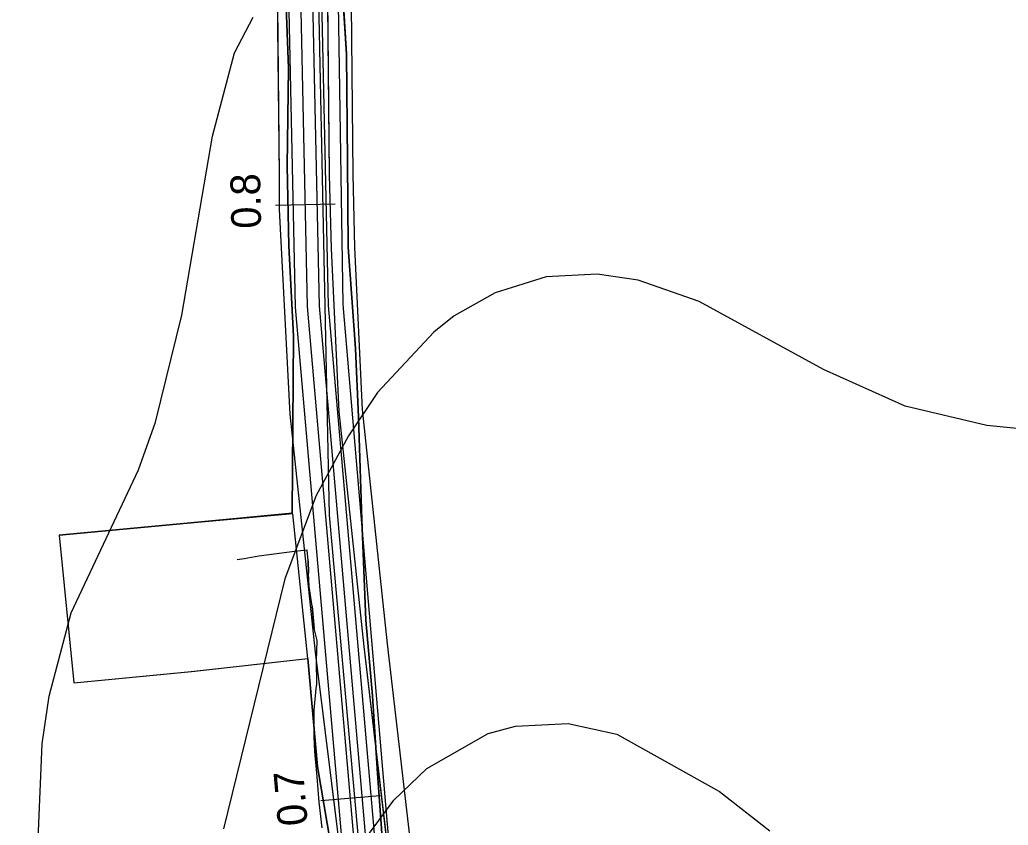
# Model space of a CAD drawing. Extents: x -662620 to -656370, y -1067090 to -1062990.
# Drawn here: x -660531.2 to -660365.2, y -1064371.3 to -1064236 of the extents above; entities that cross this region are included whole.
import ezdxf

# ---------------------------------------------------------------- set-up
doc = ezdxf.new("R2010")
doc.units = 0
for name, color, linetype in [('CESTA_ZABOR', 7, 'Continuous'), ('Default', 7, 'Continuous'), ('Krajinná_zeleň_-_liniová_-_návrh', 7, 'Continuous'), ('OBVOD_PÚ', 7, 'Continuous'), ('Ochr__pás__vod__zdroje_II__stupně', 7, 'Continuous'), ('Odvodnení_cesty_príkopem_-_navržené', 7, 'Continuous'), ('ORNÁ_PŮDA_-_STÁVAJÍCÍ', 7, 'Continuous'), ('OSTATNÍ_PLOCHA_-_NAVRŽENÁ', 7, 'Continuous'), ('OSTATNÍ_PLOCHA_-_STÁVAJÍCÍ', 7, 'Continuous'), ('POLNÍ_CESTA_NAVRŽENÁ_-_OSA', 7, 'Continuous'), ('POLNÍ_CESTA_STÁVAJÍCÍ_-_KRAJ', 7, 'Continuous'), ('SDELOVACÍ_VEDENÍ_-_PODZEMNÍ', 7, 'Continuous'), ('Trvalý_trávní_porost_-_stávající', 7, 'Continuous'), ('VRSTEVNICE_ZÁKLADNÍ', 7, 'Continuous')]:
    doc.layers.add(name, color=color, linetype=linetype)

msp = doc.modelspace()

# ---------------------------------------------------------------- linework, layer by layer
at = {"layer": 'CESTA_ZABOR'}
for p, q in [((-660487.56, -1064262.16), (-660487.99, -1064222.18)), ((-660479.6, -1064222.07), (-660479.22, -1064262.06)), ((-660487.55, -1064267.89), (-660487.56, -1064262.16)), ((-660479.22, -1064262.06), (-660478.9, -1064274.43)), ((-660485.81, -1064302.25), (-660487.55, -1064267.89)), ((-660478.9, -1064274.43), (-660477.62, -1064301.81)), ((-660481.51, -1064342.23), (-660485.81, -1064302.25)), ((-660477.62, -1064301.81), (-660473.42, -1064341.28)), ((-660476.62, -1064381.82), (-660481.51, -1064342.23)), ((-660473.42, -1064341.28), (-660468.75, -1064381.18))]:
    msp.add_line(p, q, dxfattribs=at)
for points in [[(-660476.62, -1064381.82), (-660481.51, -1064342.23), (-660485.81, -1064302.25), (-660487.55, -1064267.89), (-660487.56, -1064262.16), (-660487.99, -1064222.18), (-660488.92, -1064182.19), (-660489.62, -1064142.29), (-660490.79, -1064127.68), (-660489.61, -1064120.63), (-660489.74, -1064102.3), (-660489.62, -1064062.36), (-660491.41, -1064022.4), (-660491.82, -1063995.6), (-660491.58, -1063993.71), (-660486.92, -1063981.87), (-660480, -1063962.07), (-660476.39, -1063948.94), (-660467.64, -1063925.93), (-660459.11, -1063911.53), (-660457.57, -1063907.35), (-660441.43, -1063870.67), (-660426.53, -1063833.6), (-660410.61, -1063796.9)], [(-660402.21, -1063800.45), (-660418.38, -1063837.05), (-660433.34, -1063874.17), (-660449.71, -1063910.53), (-660464.44, -1063947.85), (-660478.91, -1063984.7), (-660482.04, -1063997.01), (-660482.49, -1064022.32), (-660480.31, -1064062.11), (-660478.98, -1064102.23), (-660479.21, -1064121.73), (-660481.5, -1064129.07), (-660481.76, -1064141.99), (-660480.35, -1064182.06), (-660479.6, -1064222.07), (-660479.22, -1064262.06), (-660478.9, -1064274.43), (-660477.62, -1064301.81), (-660473.42, -1064341.28), (-660468.75, -1064381.18)]]:
    msp.add_lwpolyline(points, dxfattribs=at)
at = {"layer": 'Krajinná_zeleň_-_liniová_-_návrh'}
msp.add_lwpolyline([(-660463.41, -1064442), (-660476.87, -1064283.86), (-660479.09, -1064143.11)], dxfattribs=at)
at = {"layer": 'OBVOD_PÚ'}
for points in [[(-660485.34, -1064319.01), (-660524.58, -1064322.57)], [(-660482.83, -1064343.31), (-660485.34, -1064319.01)], [(-660524.58, -1064322.57), (-660522.09, -1064347.37)], [(-660502.37, -1064345.51), (-660482.83, -1064343.31)], [(-660522.09, -1064347.37), (-660502.37, -1064345.51)]]:
    msp.add_lwpolyline(points, dxfattribs=at)
at = {"layer": 'Ochr__pás__vod__zdroje_II__stupně'}
msp.add_lwpolyline([(-660464.98, -1064477.66), (-660479.16, -1064319.24), (-660481.94, -1064186.81), (-660479.3, -1063994.59), (-660360.21, -1063702.35), (-660281.08, -1063700.79), (-660243.47, -1063702.35), (-660222.31, -1063711.76), (-660211.34, -1063724.29), (-660187.06, -1063774.43), (-660164.34, -1063811.26), (-660075.02, -1063846.52), (-660042.89, -1063862.97), (-660047.59, -1063878.64), (-659927.67, -1063941.34), (-659907.68, -1063958.21), (-659897.75, -1063968.57), (-659822.34, -1063992.17), (-659732.05, -1064020.39)], dxfattribs=at)
at = {"layer": 'Odvodnení_cesty_príkopem_-_navržené'}
msp.add_lwpolyline([(-660558.09, -1065055.87), (-660475.04, -1064666.65), (-660471.14, -1064652.96), (-660465.99, -1064629.97), (-660464, -1064613.86), (-660457.68, -1064584.26), (-660456.26, -1064575.18), (-660454.42, -1064557.77), (-660456.24, -1064538.9), (-660463.06, -1064471.1), (-660479.37, -1064283.99), (-660482.8, -1064124.36), (-660484.72, -1064013.14), (-660484.26, -1063999.81), (-660482.47, -1063990.24), (-660478.65, -1063978.94), (-660368.35, -1063708.74)], dxfattribs=at)
at = {"layer": 'ORNÁ_PŮDA_-_STÁVAJÍCÍ'}
for p, q in [((-660476.34, -1064241.78), (-660477.34, -1064225.29)), ((-660476.13, -1064259.82), (-660476.34, -1064241.78)), ((-660476.03, -1064274.2), (-660476.13, -1064259.82)), ((-660474.79, -1064291.24), (-660476.03, -1064274.2)), ((-660474.29, -1064302.76), (-660474.79, -1064291.24)), ((-660473.74, -1064320.03), (-660474.29, -1064302.76)), ((-660473.08, -1064336.89), (-660473.74, -1064320.03)), ((-660471.94, -1064349.57), (-660473.08, -1064336.89)), ((-660471.09, -1064362.63), (-660471.94, -1064349.57)), ((-660470.29, -1064374.22), (-660471.09, -1064362.63))]:
    msp.add_line(p, q, dxfattribs=at)
msp.add_lwpolyline([(-660470.29, -1064374.22), (-660471.09, -1064362.63), (-660471.94, -1064349.57), (-660473.08, -1064336.89), (-660473.74, -1064320.03), (-660474.29, -1064302.76), (-660474.79, -1064291.24), (-660476.03, -1064274.2), (-660476.13, -1064259.82), (-660476.34, -1064241.78), (-660477.34, -1064225.29), (-660476.74, -1064216.04), (-660477.47, -1064194.07), (-660477.33, -1064171.48), (-660477.69, -1064150.75), (-660477.81, -1064136.93), (-660478.1, -1064126.45), (-660479.89, -1064102.35), (-660481.05, -1064074.37)], dxfattribs=at)
at = {"layer": 'OSTATNÍ_PLOCHA_-_NAVRŽENÁ'}
msp.add_lwpolyline([(-660481.76, -1064141.99), (-660480.35, -1064182.06), (-660479.6, -1064222.07), (-660479.22, -1064262.06), (-660478.9, -1064274.43), (-660477.62, -1064301.81), (-660473.42, -1064341.28), (-660468.75, -1064381.18), (-660465.77, -1064421.09), (-660463.02, -1064443.82), (-660461.97, -1064448.3), (-660459.31, -1064450.58), (-660461.78, -1064420.77), (-660464.77, -1064380.8), (-660469.45, -1064340.83), (-660473.63, -1064301.5), (-660474.9, -1064274.29), (-660475.22, -1064261.99), (-660475.6, -1064222.01), (-660476.35, -1064181.95), (-660477.76, -1064141.96)], close=True, dxfattribs=at)
msp.add_lwpolyline([(-660481.76, -1064141.99), (-660480.35, -1064182.06), (-660479.6, -1064222.07), (-660479.22, -1064262.06), (-660478.9, -1064274.43), (-660477.62, -1064301.81), (-660473.42, -1064341.28), (-660468.75, -1064381.18), (-660465.77, -1064421.09), (-660463.02, -1064443.82), (-660461.97, -1064448.3), (-660459.31, -1064450.58), (-660461.78, -1064420.77), (-660464.77, -1064380.8), (-660469.45, -1064340.83), (-660473.63, -1064301.5), (-660474.9, -1064274.29), (-660475.22, -1064261.99), (-660475.6, -1064222.01), (-660476.35, -1064181.95), (-660477.76, -1064141.96)], close=True, dxfattribs=at)
at = {"layer": 'OSTATNÍ_PLOCHA_-_STÁVAJÍCÍ'}
for p, q in [((-660477.34, -1064225.29), (-660476.34, -1064241.78)), ((-660477.34, -1064225.29), (-660476.34, -1064241.78)), ((-660486.09, -1064244.12), (-660486.67, -1064227.81)), ((-660486.09, -1064244.12), (-660486.67, -1064227.81)), ((-660476.34, -1064241.78), (-660476.13, -1064259.82)), ((-660476.34, -1064241.78), (-660476.13, -1064259.82)), ((-660486.31, -1064260.54), (-660486.09, -1064244.12)), ((-660486.31, -1064260.54), (-660486.09, -1064244.12)), ((-660476.13, -1064259.82), (-660476.03, -1064274.2)), ((-660476.13, -1064259.82), (-660476.03, -1064274.2)), ((-660485.99, -1064273.97), (-660486.31, -1064260.54)), ((-660485.99, -1064273.97), (-660486.31, -1064260.54)), ((-660485.23, -1064289.19), (-660485.99, -1064273.97)), ((-660485.23, -1064289.19), (-660485.99, -1064273.97)), ((-660476.03, -1064274.2), (-660474.79, -1064291.24)), ((-660476.03, -1064274.2), (-660474.79, -1064291.24)), ((-660485.42, -1064318.9), (-660485.23, -1064289.19)), ((-660485.42, -1064318.9), (-660485.23, -1064289.19)), ((-660474.79, -1064291.24), (-660474.29, -1064302.76)), ((-660474.79, -1064291.24), (-660474.29, -1064302.76)), ((-660474.29, -1064302.76), (-660473.74, -1064320.03)), ((-660474.29, -1064302.76), (-660473.74, -1064320.03)), ((-660485.34, -1064319.01), (-660524.58, -1064322.57)), ((-660485.34, -1064319.01), (-660524.58, -1064322.57)), ((-660499.48, -1064320.24), (-660485.42, -1064318.9)), ((-660499.48, -1064320.24), (-660485.42, -1064318.9)), ((-660482.83, -1064343.31), (-660485.34, -1064319.01)), ((-660482.83, -1064343.31), (-660485.34, -1064319.01)), ((-660524.58, -1064322.57), (-660499.48, -1064320.24)), ((-660524.58, -1064322.57), (-660499.48, -1064320.24)), ((-660473.74, -1064320.03), (-660473.08, -1064336.89)), ((-660473.74, -1064320.03), (-660473.08, -1064336.89)), ((-660473.08, -1064336.89), (-660471.94, -1064349.57)), ((-660473.08, -1064336.89), (-660471.94, -1064349.57)), ((-660481.22, -1064361.46), (-660482.83, -1064343.31)), ((-660481.22, -1064361.46), (-660482.83, -1064343.31)), ((-660471.94, -1064349.57), (-660471.09, -1064362.63)), ((-660471.94, -1064349.57), (-660471.09, -1064362.63)), ((-660479.03, -1064374.35), (-660481.22, -1064361.46)), ((-660479.03, -1064374.35), (-660481.22, -1064361.46)), ((-660471.09, -1064362.63), (-660470.29, -1064374.22)), ((-660471.09, -1064362.63), (-660470.29, -1064374.22))]:
    msp.add_line(p, q, dxfattribs=at)
for points in [[(-660479.03, -1064374.35), (-660481.22, -1064361.46), (-660482.83, -1064343.31), (-660485.34, -1064319.01), (-660524.58, -1064322.57), (-660499.48, -1064320.24), (-660485.42, -1064318.9), (-660485.23, -1064289.19), (-660485.99, -1064273.97), (-660486.31, -1064260.54), (-660486.09, -1064244.12), (-660486.67, -1064227.81), (-660486.64, -1064217.91), (-660487.12, -1064191.78), (-660487.32, -1064171.49), (-660492.89, -1064153.57), (-660495.19, -1064153.41), (-660498.07, -1064140.85), (-660505.56, -1064125.57), (-660511.66, -1064112.29), (-660520.43, -1064100.97), (-660529.29, -1064080.76), (-660534.95, -1064065.62)], [(-660479.03, -1064374.35), (-660481.22, -1064361.46), (-660482.83, -1064343.31), (-660485.34, -1064319.01), (-660524.58, -1064322.57), (-660499.48, -1064320.24), (-660485.42, -1064318.9), (-660485.23, -1064289.19), (-660485.99, -1064273.97), (-660486.31, -1064260.54), (-660486.09, -1064244.12), (-660486.67, -1064227.81), (-660486.64, -1064217.91), (-660487.12, -1064191.78), (-660487.32, -1064171.49), (-660492.89, -1064153.57), (-660495.19, -1064153.41), (-660498.07, -1064140.85), (-660505.56, -1064125.57), (-660511.66, -1064112.29), (-660520.43, -1064100.97), (-660529.29, -1064080.76), (-660534.95, -1064065.62)], [(-660481.05, -1064074.37), (-660479.89, -1064102.35), (-660478.1, -1064126.45), (-660477.81, -1064136.93), (-660477.69, -1064150.75), (-660477.33, -1064171.48), (-660477.47, -1064194.07), (-660476.74, -1064216.04), (-660477.34, -1064225.29), (-660476.34, -1064241.78), (-660476.13, -1064259.82), (-660476.03, -1064274.2), (-660474.79, -1064291.24), (-660474.29, -1064302.76), (-660473.74, -1064320.03), (-660473.08, -1064336.89), (-660471.94, -1064349.57), (-660471.09, -1064362.63), (-660470.29, -1064374.22)], [(-660481.05, -1064074.37), (-660479.89, -1064102.35), (-660478.1, -1064126.45), (-660477.81, -1064136.93), (-660477.69, -1064150.75), (-660477.33, -1064171.48), (-660477.47, -1064194.07), (-660476.74, -1064216.04), (-660477.34, -1064225.29), (-660476.34, -1064241.78), (-660476.13, -1064259.82), (-660476.03, -1064274.2), (-660474.79, -1064291.24), (-660474.29, -1064302.76), (-660473.74, -1064320.03), (-660473.08, -1064336.89), (-660471.94, -1064349.57), (-660471.09, -1064362.63), (-660470.29, -1064374.22)]]:
    msp.add_lwpolyline(points, dxfattribs=at)
at = {"layer": 'POLNÍ_CESTA_NAVRŽENÁ_-_OSA'}
for points in [[(-660561.51, -1065055.14), (-660462.91, -1064592.2), (-660459.73, -1064574.68), (-660457.94, -1064557.76), (-660459.73, -1064539.24), (-660466.54, -1064471.42), (-660482.86, -1064284.18), (-660486.3, -1064124.42), (-660488.22, -1064013.11), (-660487.75, -1063999.42), (-660485.86, -1063989.36), (-660481.93, -1063977.72), (-660371.59, -1063707.42)], [(-660488.23, -1064267.16), (-660478.23, -1064266.94)], [(-660480.65, -1064367.17), (-660470.69, -1064366.3)]]:
    msp.add_lwpolyline(points, dxfattribs=at)
at = {"layer": 'POLNÍ_CESTA_STÁVAJÍCÍ_-_KRAJ'}
for points in [[(-660563.47, -1065054.73), (-660464.88, -1064591.81), (-660461.71, -1064574.4), (-660459.95, -1064557.75), (-660461.72, -1064539.44), (-660468.53, -1064471.61), (-660484.86, -1064284.29), (-660488.3, -1064124.46), (-660490.22, -1064013.09), (-660489.75, -1063999.2), (-660487.8, -1063988.85), (-660483.81, -1063977.02), (-660477.71, -1063961.92), (-660474.07, -1063948.91), (-660465.37, -1063926.71), (-660457.21, -1063913), (-660373.44, -1063706.66)], [(-660559.56, -1065055.56), (-660475.57, -1064663), (-660472.75, -1064654.02), (-660466.98, -1064628.93), (-660465.02, -1064612.2), (-660460.95, -1064592.59), (-660457.75, -1064574.96), (-660455.93, -1064557.77), (-660457.74, -1064539.05), (-660464.55, -1064471.24), (-660480.86, -1064284.07), (-660484.3, -1064124.39), (-660486.22, -1064013.13), (-660485.76, -1063999.64), (-660483.92, -1063989.86), (-660480.06, -1063978.41), (-660369.74, -1063708.17)]]:
    msp.add_lwpolyline(points, dxfattribs=at)
at = {"layer": 'SDELOVACÍ_VEDENÍ_-_PODZEMNÍ'}
for points in [[(-660480.41, -1064371.73), (-660480.94, -1064367.42), (-660481.27, -1064363.16), (-660481.65, -1064358.9), (-660481.73, -1064356.38), (-660481.75, -1064351.96), (-660481.43, -1064348.35), (-660481.29, -1064347.61), (-660481.35, -1064343.72), (-660481.25, -1064340.31), (-660481.78, -1064338.28), (-660482.1, -1064334.53), (-660482.58, -1064331.19), (-660482.71, -1064328.98), (-660482.75, -1064326.92), (-660482.93, -1064325.12), (-660485.08, -1064325.32), (-660491.04, -1064326.11), (-660493.49, -1064326.55), (-660494.7, -1064326.72)], [(-660480.41, -1064371.73), (-660480.94, -1064367.42), (-660481.27, -1064363.16), (-660481.65, -1064358.9), (-660481.73, -1064356.38), (-660481.75, -1064351.96), (-660481.43, -1064348.35), (-660481.29, -1064347.61), (-660481.35, -1064343.72), (-660481.25, -1064340.31), (-660481.78, -1064338.28), (-660482.1, -1064334.53), (-660482.58, -1064331.19), (-660482.71, -1064328.98), (-660482.75, -1064326.92), (-660482.93, -1064325.12), (-660485.08, -1064325.32), (-660491.04, -1064326.11), (-660493.49, -1064326.55), (-660494.7, -1064326.72)], [(-660482.75, -1064326.92), (-660482.71, -1064328.98)], [(-660482.75, -1064326.92), (-660482.71, -1064328.98)], [(-660482.1, -1064334.53), (-660481.78, -1064338.28)], [(-660482.1, -1064334.53), (-660481.78, -1064338.28)]]:
    msp.add_lwpolyline(points, dxfattribs=at)
at = {"layer": 'Trvalý_trávní_porost_-_stávající'}
for p, q in [((-660486.67, -1064227.81), (-660486.09, -1064244.12)), ((-660486.09, -1064244.12), (-660486.31, -1064260.54)), ((-660486.31, -1064260.54), (-660485.99, -1064273.97)), ((-660485.99, -1064273.97), (-660485.23, -1064289.19)), ((-660485.23, -1064289.19), (-660485.42, -1064318.9)), ((-660485.42, -1064318.9), (-660499.48, -1064320.24)), ((-660499.48, -1064320.24), (-660524.58, -1064322.57)), ((-660524.58, -1064322.57), (-660522.09, -1064347.37)), ((-660502.38, -1064345.51), (-660482.83, -1064343.31)), ((-660482.83, -1064343.31), (-660481.22, -1064361.46)), ((-660522.09, -1064347.37), (-660502.38, -1064345.51)), ((-660481.22, -1064361.46), (-660479.03, -1064374.35))]:
    msp.add_line(p, q, dxfattribs=at)
msp.add_lwpolyline([(-660534.95, -1064065.62), (-660529.29, -1064080.76), (-660520.43, -1064100.97), (-660511.66, -1064112.29), (-660505.56, -1064125.57), (-660498.07, -1064140.85), (-660495.19, -1064153.41), (-660492.89, -1064153.57), (-660487.32, -1064171.49), (-660487.12, -1064191.78), (-660486.64, -1064217.91), (-660486.67, -1064227.81), (-660486.09, -1064244.12), (-660486.31, -1064260.54), (-660485.99, -1064273.97), (-660485.23, -1064289.19), (-660485.42, -1064318.9), (-660499.48, -1064320.24), (-660524.58, -1064322.57), (-660522.09, -1064347.37), (-660502.38, -1064345.51), (-660482.83, -1064343.31), (-660481.22, -1064361.46), (-660479.03, -1064374.35)], dxfattribs=at)
at = {"layer": 'VRSTEVNICE_ZÁKLADNÍ'}
for points in [[(-660528.42, -1064381.66), (-660527.42, -1064357.65), (-660526.28, -1064349.64), (-660522.56, -1064335.64), (-660511.27, -1064311.62), (-660508.41, -1064303.62), (-660503.98, -1064285.61), (-660498.84, -1064255.59), (-660495.12, -1064241.59), (-660491.97, -1064235.58)], [(-660528.42, -1064381.66), (-660527.42, -1064357.65), (-660526.28, -1064349.64), (-660522.56, -1064335.64), (-660511.27, -1064311.62), (-660508.41, -1064303.62), (-660503.98, -1064285.61), (-660498.84, -1064255.59), (-660495.12, -1064241.59), (-660491.97, -1064235.58)], [(-660343.04, -1064306.76), (-660368.77, -1064304.19), (-660382.49, -1064300.9), (-660396.21, -1064294.76), (-660417.08, -1064283.32), (-660427.37, -1064279.75), (-660434.23, -1064278.75), (-660442.81, -1064279.18), (-660451.38, -1064281.89), (-660458.24, -1064285.75), (-660461.67, -1064288.47), (-660471.11, -1064298.62), (-660475.96, -1064305.91), (-660481.4, -1064315.91), (-660486.69, -1064329.92), (-660496.98, -1064371.94)], [(-660343.04, -1064306.76), (-660368.77, -1064304.19), (-660382.49, -1064300.9), (-660396.21, -1064294.76), (-660417.08, -1064283.32), (-660427.37, -1064279.75), (-660434.23, -1064278.75), (-660442.81, -1064279.18), (-660451.38, -1064281.89), (-660458.24, -1064285.75), (-660461.67, -1064288.47), (-660471.11, -1064298.62), (-660475.96, -1064305.91), (-660481.4, -1064315.91), (-660486.69, -1064329.92), (-660496.98, -1064371.94)], [(-660473.39, -1064373.94), (-660468.39, -1064367.08), (-660462.82, -1064361.79), (-660452.53, -1064355.93), (-660447.95, -1064354.65), (-660439.09, -1064354.22), (-660430.91, -1064355.99), (-660413.68, -1064365.65), (-660405.21, -1064372.23)]]:
    msp.add_lwpolyline(points, dxfattribs=at)

# ---------------------------------------------------------------- texts
at = {"layer": 'Default'}
for s, rotation, p in [('0.8', 91.232, (-660490.65, -1064271.06)), ('0.7', 94.9811, (-660482.81, -1064371.22))]:
    msp.add_text(s, height=5, rotation=rotation, dxfattribs=at).set_placement(p)

doc.saveas('drawing.dxf')
